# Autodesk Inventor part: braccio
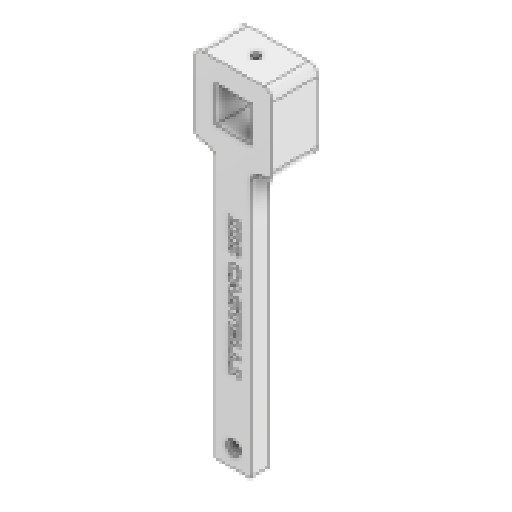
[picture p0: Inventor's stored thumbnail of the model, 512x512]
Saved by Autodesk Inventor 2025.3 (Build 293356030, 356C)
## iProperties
Created: 2025-09
Part Number: braccio
Material: Plastica ABS
Document SubType Name: Modeling
Designer: Ryzen5700u
Density: 1.06 g/cm^3
Appearance: Liscia - Bianco
Author: Ryzen5700u
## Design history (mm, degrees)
sketch "Schizzo1"
  geometry: L1 (-10.05, -10.05)-(10.05, -10.05); L2 (10.05, -10.05)-(10.05, 10.05); L3 (10.05, 10.05)-(-10.05, 10.05); L4 (-10.05, 10.05)-(-10.05, -10.05); L5 (-10.05, -10.05)-(10.05, 10.05); L6 (10.05, -10.05)-(-10.05, 10.05); L7 (-22, -22)-(22, -22); L8 (22, -22)-(22, 22); L9 (22, 22)-(-22, 22); L10 (-22, 22)-(-22, -22); L11 (-22, -22)-(22, 22); L12 (22, -22)-(-22, 22); L13 (-10, -22)-(10, -22); L14 (10, -22)-(10, -172); L15 (10, -172)-(-10, -172); L16 (-10, -172)-(-10, -22); 2 further points
  constraints: 32 end point, 6 parallel, 4 midpoint, 3 horizontal, 3 perpendicular, 1 point on line
  dimensions: "d0" = 20.1 distance of L3.end L2.end; "d1" = 20.1 distance of L2.end L1.end; "d2" = 44 distance of L9.end L8.end; "d3" = 44 distance of L7.end L8.end; "d4" = 150 distance of L13.end L14.end
extrude "Estrusione1" new body sketch "Schizzo1" distance "d5" = 10; taper "d6" = 0 deg
sketch "Schizzo2"
  geometry: L1 (22, -22)-(10, -22) reference; L2 (22, 22)-(22, -22) reference; L3 (-22, 22)-(22, 22) reference; L4 (-22, -22)-(-22, 22) reference; L5 (-10, -22)-(-22, -22) reference; L6 (-10, -172)-(-10, -22) reference; L7 (10, -172)-(-10, -172) reference; L8 (10, -22)-(10, -172) reference; L9 (10.05, -10.05)-(10.05, 10.05) reference; L10 (-10.05, -10.05)-(10.05, -10.05) reference; L11 (-10.05, 10.05)-(-10.05, -10.05) reference; L12 (10.05, 10.05)-(-10.05, 10.05) reference; L13 (10, -22)-(-10, -22); 1 further point
  constraints: 2 end point, 1 horizontal
extrude "Estrusione2" join sketch "Schizzo2" distance "d7" = 15; taper "d8" = 0 deg
sketch "Schizzo3"
  geometry: L1 (44, 25)-(44, 0) reference; L2 (44, 25)-(0, 25) reference; L3 (44, 0)-(0, 25); L4 (0, 0)-(0, 25) reference; L5 (0, 25)-(0, 0); L6 (0, 0)-(44, 25); 2 further points
  constraints: 6 end point, 2 midpoint, 1 collinear
hole "Foro1" sketch "Schizzo3" at (22, 12.5) diameter "d9" = 4.5; stored, may be unused: countersink angle "d13" = 90 deg, drill point angle "d15" = 118 deg; dims "d10" = 6, "d11" = 10, "d12" = 5.7, "d14" = 64.25
fillet "Raccordo1" dims "d16" = 5
sketch "Schizzo4"
  geometry: L1 (4.5, -162)-(2.25, -165.897); L2 (2.25, -165.897)-(-2.25, -165.897); L3 (-2.25, -165.897)-(-4.5, -162); L4 (-4.5, -162)-(-2.25, -158.103); L5 (-2.25, -158.103)-(2.25, -158.103); L6 (2.25, -158.103)-(4.5, -162); C1 r 4 at (0, -162) reference; 2 further points
  constraints: 12 end point, 1 coincident, 13 other
  dimensions: "d21" = 4.5 distance of L4.end L5.end
extrude "Estrusione3" cut sketch "Schizzo4" distance "d17" = 4; taper "d18" = 0 deg
sketch "Schizzo5"
  geometry: C1 r 2.25 at (0, -162) reference; 1 further point
extrude "Estrusione4" cut sketch "Schizzo5" extent not by distance; stored distance "d19" = 4; taper "d20" = 0 deg
sketch "Schizzo6"
  geometry: L1 (3.332, -49.867)-(3.332, -144.876); L2 (3.332, -144.876)-(-4.284, -144.876); L3 (-4.284, -144.876)-(-4.284, -49.867); L4 (-4.284, -49.867)-(3.332, -49.867); 1 further point
  constraints: 2 other
extrude "Estrusione5" cut sketch "Schizzo6" distance "d23" = 0.2; taper "d24" = 0 deg
fillet "Raccordo3" dims "d25" = 15
fillet "Raccordo4" dims "d26" = 1
node "Solido1"
node "Linea chiusa proiettata1"
node "Riferimento1"
node "Riferimento2"
